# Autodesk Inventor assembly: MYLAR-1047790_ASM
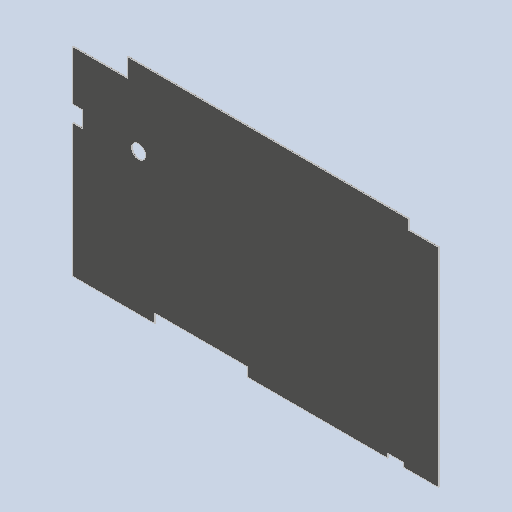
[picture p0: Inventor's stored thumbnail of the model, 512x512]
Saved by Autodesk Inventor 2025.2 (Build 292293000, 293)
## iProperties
Created: 2025-04
Part Number: MYLAR-1047790_ASM
Description: NOT SPECIFIED
Document SubType Name: Assembly
Designer: BennF
Author: BennF
Revision Number: 3LAST_VERSION
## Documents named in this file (2)
- C:\Users\BennF\Nextcloud\Benutzer\CNC JarBeRi\existing parts\Electronics\Powersupply LRS-150-24\LRS-150(230808)\LRS-150(230808)\MYLAR-1047790_ASM.iam
- C:\Users\BennF\Nextcloud\Benutzer\CNC JarBeRi\existing parts\Electronics\Powersupply LRS-150-24\LRS-150(230808)\LRS-150(230808)\MYLAR-1047460.ipt
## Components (1 placed, 1 different names)
1. MYLAR-1047460_29
